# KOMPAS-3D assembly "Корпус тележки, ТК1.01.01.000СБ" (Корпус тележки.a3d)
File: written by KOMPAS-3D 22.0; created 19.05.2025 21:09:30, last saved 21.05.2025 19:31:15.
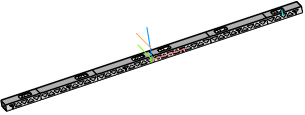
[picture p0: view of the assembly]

Document properties: Автор: user; Полное имя файла: КД\ТК1.01.01.000 СБ - Корпус тележки.cdw

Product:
- Component [detail]: Стенка боковая  | designation ТК1.01.01.001-01  | qty 1  | pos. 2  | Масса: 11.528421; source file: КД\Стенка боковая.cdw, Стенка боковая.cdw, Стенка боковая.m3d
- Component [detail]: Стенка боковая  | designation ТК1.01.01.001  | qty 1  | pos. 1  | Масса: 11.51708; source file: КД\Стенка боковая.cdw, Стенка боковая.cdw, Стенка боковая.m3d
- Component [detail]: Ребро продольное  | designation ТК1.01.01.004  | qty 2  | pos. 5  | Масса: 0.575358; source file: КД\Чертеж Ребро продольное.cdw, Ребро продольное.cdw, Ребро продольное.m3d
- Component [detail]: Ребро продольное  | designation ТК1.01.01.004-01  | qty 5  | pos. 6  | Масса: 0.574941; source file: КД\Чертеж Ребро продольное.cdw, Ребро продольное _ -01.cdw, Ребро продольное.cdw, Ребро продольное.m3d
- Component [detail]: Верхняя пластина  | designation ТК1.01.01.003  | qty 1  | pos. 4  | Масса: 41.469866; Форматы листов документа: A4@4~3; source file: Верхняя пластина.cdw, Верхняя пластина.m3d, КД\Верхняя пластина.cdw
- Component [detail]: Пластина нижняя  | designation ТК1.01.01.002  | qty 1  | pos. 3  | Масса: 26.939167; Форматы листов документа: A3; source file: КД\ТК1.01.01.002 - Пластина нижняя.cdw, Корпус тележки\КД\ТК1.01.01.002 - Пластина нижняя.cdw, Корпус тележки\Пластина нижняя.cdw, Пластина нижняя.m3d
- Component [standard]: Гайка М12-6H(S18) ГОСТ 5915-70  | qty 2  | pos. 7  | Масса: 0.01567; Раздел спецификации: Стандартные изделия; Рассекать на разрезах: no; additional columns: М12-6H (S18)
- Part/product: Корпус тележки  | designation ТК1.01.01.000СБ
    Масса: 95.511296
    Форматы листов документа: A4@4~3
    source file: КД\ТК1.01.01.000 - Корпус тележки.spw

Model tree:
1. Линейный размер:1  (with: Элемент выдавливания:1)
     Значение = 166
2. Эскиз:1  (with: Элемент выдавливания:8, Элемент выдавливания:1)
3. Массив по сетке:1  (with: Элемент выдавливания:1)  (5 pattern instances)
     Угол раствора = 90
4. Линейный размер:2  (with: Элемент выдавливания:1)
     Значение = 1
5. Средняя плоскость:1  (with: Элемент выдавливания:1, Элемент выдавливания:8, Элемент выдавливания:7, Элемент выдавливания:2, Элемент выдавливания:6)
     Расстояние = -83; Ориентация = 2; Ориентация = 2; Ориентация = 2

Referenced files in D:\Работа\2025\5. Май\Задание №6 - Тележка для крыши\3Д\Тележка в сборе\Корпус тележки\: Стенка боковая.m3d, Стенка боковая.cdw, Ребро продольное.m3d, Ребро продольное.cdw, Ребро продольное _ -01.cdw, Верхняя пластина.m3d, Верхняя пластина.cdw, Пластина нижняя.m3d
Referenced files in D:\Работа\2025\5. Май\Задание №6 - Тележка для крыши\3Д\Тележка в сборе\Корпус тележки\КД\: Стенка боковая.cdw, Чертеж Ребро продольное.cdw, Верхняя пластина.cdw, ТК1.01.01.002 - Пластина нижняя.cdw
Referenced files in D:\Работа\2025\5. Май\Задание №6 - Тележка для крыши\3Д\Тележка в сборе\Корпус тележки\Корпус тележки\: Пластина нижняя.cdw
Referenced files in D:\Работа\2025\5. Май\Задание №6 - Тележка для крыши\3Д\Тележка в сборе\Корпус тележки\Корпус тележки\КД\: ТК1.01.01.002 - Пластина нижняя.cdw
Referenced files in C:\Program Files\ASCON\KOMPAS-3D v22\Libs\PolynomLib\DATA\vault\Methods\Kompas\3D\: PLib_Nut_OST92_900.m3d
Referenced files in D:\Работа\2025\5. Май\Задание №6 - Тележка для крыши\3Д\Корпус тележки\: Ребро продольное.m3d
Referenced files in D:\Program Files\ASCON\KOMPAS-3D v22\Libs\PolynomLib\DATA\vault\Methods\Kompas\3D\: PLib_Nut_OST92_900.m3d
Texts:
  ТК1.01.01.001 - 01
  ТК1.01.01.001
  ТК1.01.01.004
  ТК1.01.01.004 - 01
  ТК1.01.01.003
  ТК1.01.01.002
  Крепежное изделие ГОСТ
  BOSimple***PART:26b7db98-4be1-8179-e7df-2046e24e1536***SHORTLOC:Root±30±10±20±©{}110±10±50±60[Нет;Без покрытия;Без указания материала;-;12;1,75;18]
  Точка начала. Х
  Точка начала. Y
  Точка начала. Z
  ТК1.01.01.000
  ТК1.01.01.000 СБ
  ТК1.01.01.001-01 Стенка боковая
  ТК1.01.01.001 Стенка боковая
  ТК1.01.01.004 Ребро продольное (1)
  ТК1.01.01.004-01 Ребро продольное (1)
  ТК1.01.01.004 Ребро продольное (2)
  ТК1.01.01.003 Верхняя пластина
  ТК1.01.01.002 Пластина нижняя
  Гайка М12-6H(S18) ГОСТ 5915-70 (1)
  bcut1
  hole1
  hcut1
  hole2
  cut1
  Гайка М12-6H(S18) ГОСТ 5915-70 (2)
